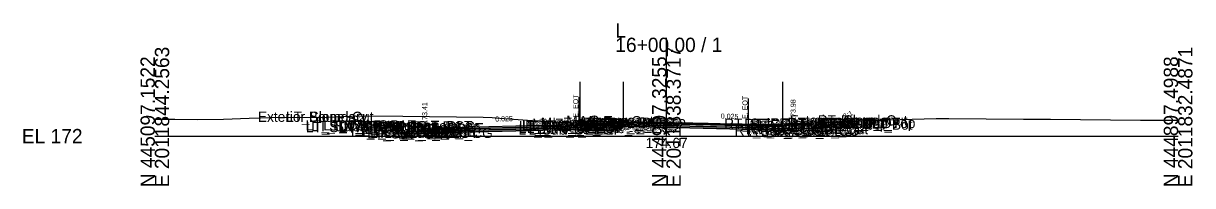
# Model space of a CAD drawing. Extents: x -26 to 4203, y -10 to 9526.
# Drawn here: x -25.7 to 202.8, y 5990.3 to 6022.1 of the extents above; entities that cross this region are included whole.
import ezdxf

# ---------------------------------------------------------------- set-up
doc = ezdxf.new("R2010")
doc.units = 0
for name, color, linetype in [('Default', 7, 'Continuous'), ('Exist Cross Section Cell', 7, 'Continuous'), ('Exist XS Center Line Elevation Label', 7, 'Continuous'), ('Exist XS Ground Line', 7, 'Continuous'), ('Prop CMT Conc Surface', 7, 'Continuous'), ('Prop CMT Concrete Structures', 7, 'Continuous'), ('Prop CMT Pvmt Course 1', 7, 'Continuous'), ('Prop CMT Pvmt Course 1 CG', 7, 'Continuous'), ('Prop CMT Pvmt Course 2', 7, 'Continuous'), ('Prop CMT Pvmt Course 3', 7, 'Continuous'), ('Prop CMT Pvmt Surface', 7, 'Continuous'), ('Prop CMT Slope Grass', 7, 'Continuous'), ('Prop CMT Subgrade Earthwork', 7, 'Continuous'), ('Prop XS Hydro Elevations', 7, 'Continuous'), ('Prop XS Label Text', 7, 'Continuous'), ('Prop XS SE Text', 7, 'Continuous'), ('Prop XS Side Slope Text', 7, 'Continuous'), ('Scratch_Level_0', 7, 'Continuous'), ('Scratch_Level_3', 7, 'Continuous')]:
    doc.layers.add(name, color=color, linetype=linetype)

msp = doc.modelspace()

# ---------------------------------------------------------------- linework, layer by layer
at = {"layer": 'Exist Cross Section Cell'}
for p, q in [((100, 6000), (100, 6019.26)), ((0, 6000), (100, 6000)), ((100, 6000), (200, 6000))]:
    msp.add_line(p, q, dxfattribs=at)
at = {"layer": 'Exist XS Ground Line'}
msp.add_lwpolyline([(0, 6003.3), (3.93, 6003.34), (8.4, 6003.25), (13.39, 6003.33), (18.42, 6003.52), (22.85, 6003.62), (28.44, 6003.68), (32.31, 6003.64), (38.46, 6003.89), (41.77, 6003.96), (48.48, 6003.9), (64.15, 6003.68), (65.91, 6003.65), (66.51, 6003.6), (76.4, 6002.89), (81.51, 6002.6), (82.34, 6002.6), (82.87, 6002.6), (84.32, 6002.6), (84.76, 6002.61), (86.85, 6002.6), (87.23, 6002.6), (89.24, 6002.63), (89.76, 6002.64), (91.62, 6002.63), (92.28, 6002.64), (92.77, 6002.65), (94.08, 6002.67), (94.78, 6002.67), (96.34, 6002.66), (97.26, 6002.66), (98.31, 6002.66), (100, 6002.67), (100.98, 6002.65), (102.28, 6002.62), (103.62, 6002.6), (105.17, 6002.58), (106.42, 6002.54), (107.24, 6002.52), (108.12, 6002.5), (109.75, 6002.48), (110.5, 6002.46), (112.27, 6002.4), (114.28, 6002.38), (114.77, 6002.37), (115.96, 6002.34), (117.15, 6002.3), (117.52, 6002.29), (124.56, 6002.47), (128.63, 6002.62), (130.55, 6002.71), (138.65, 6003.04), (152.71, 6003.45), (153.51, 6003.46), (155.19, 6003.44), (169.8, 6003.33), (171.37, 6003.34), (175.06, 6003.3), (192.64, 6003.15), (194.12, 6003.14), (197.4, 6003.13), (200, 6003.12)], dxfattribs=at)
at = {"layer": 'Prop CMT Conc Surface'}
for points in [[(48.25, 6002), (43.25, 6002.1)], [(52.75, 6001.41), (52.75, 6001.91), (52.25, 6001.91)], [(54.75, 6001.54), (52.75, 6001.41)], [(122.76, 6002.11), (124.76, 6001.98)], [(124.76, 6001.98), (124.76, 6002.48), (125.26, 6002.48)], [(129.26, 6002.57), (134.26, 6002.67)]]:
    msp.add_lwpolyline(points, dxfattribs=at)
at = {"layer": 'Prop CMT Concrete Structures'}
for p, q in [((83.85, 6002.77), (83.11, 6002.5)), ((83.11, 6002.5), (83.11, 6002.33)), ((88.1, 6003.24), (83.85, 6002.77)), ((90.84, 6003.28), (88.1, 6003.24)), ((91.6, 6003.05), (90.84, 6003.28)), ((91.61, 6002.88), (91.6, 6003.05))]:
    msp.add_line(p, q, dxfattribs=at)
for points in [[(43.25, 6001.77), (43.25, 6002.1)], [(43.25, 6002.1), (48.25, 6002)], [(48.25, 6001.67), (43.25, 6001.77)], [(48.25, 6002), (48.25, 6001.67)], [(54.75, 6001.54), (52.75, 6001.41), (52.75, 6001.91), (52.25, 6001.91)], [(52.25, 6001.91), (52.25, 6000.9), (54.75, 6000.96)], [(54.75, 6000.96), (54.75, 6001.54)], [(83.11, 6002.33), (91.61, 6002.88)], [(122.76, 6002.11), (124.76, 6001.98), (124.76, 6002.48), (125.26, 6002.48)], [(125.26, 6002.48), (125.26, 6001.46), (122.76, 6001.52)], [(122.76, 6001.52), (122.76, 6002.11)], [(134.26, 6002.67), (129.26, 6002.57)], [(129.26, 6002.57), (129.26, 6002.23)], [(129.26, 6002.23), (134.26, 6002.33)], [(134.26, 6002.33), (134.26, 6002.67)]]:
    msp.add_lwpolyline(points, dxfattribs=at)
at = {"layer": 'Prop CMT Pvmt Course 1'}
for points in [[(81.09, 6002.2), (54.75, 6001.54)], [(54.75, 6001.29), (81.09, 6001.95)], [(54.75, 6001.54), (54.75, 6001.29)], [(81.09, 6002.2), (91.61, 6002.88)], [(91.61, 6002.63), (81.09, 6001.95)], [(81.09, 6001.95), (81.09, 6002.2)], [(81.09, 6001.95), (81.09, 6002.2)], [(91.61, 6002.88), (122.76, 6002.11)], [(91.61, 6002.63), (91.61, 6002.88)], [(91.61, 6002.63), (91.61, 6002.88)], [(122.76, 6001.86), (91.61, 6002.63)], [(122.76, 6002.11), (122.76, 6001.86)]]:
    msp.add_lwpolyline(points, dxfattribs=at)
for points in [[(81.09, 6001.95), (81.09, 6002.08), (81.09, 6002.08), (81.09, 6001.95)], [(91.61, 6002.63), (91.61, 6002.76), (91.61, 6002.76), (91.61, 6002.63)]]:
    msp.add_lwpolyline(points, close=True, dxfattribs=at)
at = {"layer": 'Prop CMT Pvmt Course 1 CG'}
for points in [[(122.76, 6001.52), (125.76, 6001.45), (126.1, 6001.1)], [(122.76, 6001.19), (122.76, 6001.52)], [(54.75, 6000.96), (51.75, 6000.88), (51.41, 6000.54)], [(51.41, 6000.54), (54.75, 6000.63)], [(54.75, 6000.63), (54.75, 6000.96)], [(126.1, 6001.1), (122.76, 6001.19)]]:
    msp.add_lwpolyline(points, dxfattribs=at)
at = {"layer": 'Prop CMT Pvmt Course 2'}
for points in [[(81.09, 6001.95), (54.75, 6001.29)], [(54.75, 6000.96), (81.09, 6001.62)], [(54.75, 6001.29), (54.75, 6000.96)], [(81.09, 6001.95), (91.61, 6002.63)], [(91.61, 6002.3), (81.09, 6001.62)], [(81.09, 6001.62), (81.09, 6001.95)], [(81.09, 6001.62), (81.09, 6001.95)], [(91.61, 6002.63), (122.76, 6001.86)], [(91.61, 6002.3), (91.61, 6002.63)], [(91.61, 6002.3), (91.61, 6002.63)], [(122.76, 6001.52), (91.61, 6002.3)], [(122.76, 6001.86), (122.76, 6001.52)]]:
    msp.add_lwpolyline(points, dxfattribs=at)
at = {"layer": 'Prop CMT Pvmt Course 3'}
for points in [[(81.09, 6001.62), (54.75, 6000.96)], [(54.75, 6000.63), (81.09, 6001.28)], [(81.09, 6001.62), (91.61, 6002.3)], [(91.61, 6001.97), (81.09, 6001.28)], [(81.09, 6001.28), (81.09, 6001.62)], [(81.09, 6001.28), (81.09, 6001.62)], [(91.61, 6002.3), (122.76, 6001.52)], [(91.61, 6001.97), (91.61, 6002.3)], [(91.61, 6001.97), (91.61, 6002.3)], [(122.76, 6001.19), (91.61, 6001.97)], [(122.76, 6001.52), (122.76, 6001.19)], [(54.75, 6000.96), (54.75, 6000.63)]]:
    msp.add_lwpolyline(points, dxfattribs=at)
at = {"layer": 'Prop CMT Pvmt Surface'}
for points in [[(81.09, 6002.2), (54.75, 6001.54)], [(81.09, 6002.2), (91.61, 6002.88)], [(91.61, 6002.88), (122.76, 6002.11)]]:
    msp.add_lwpolyline(points, dxfattribs=at)
at = {"layer": 'Prop CMT Slope Grass'}
for p, q in [((37.5, 6003.85), (42.75, 6002.1)), ((134.76, 6002.67), (135.5, 6002.91))]:
    msp.add_line(p, q, dxfattribs=at)
for points in [[(52.25, 6001.91), (42.75, 6002.1)], [(125.26, 6002.48), (134.26, 6002.66)], [(134.26, 6002.66), (134.76, 6002.67)]]:
    msp.add_lwpolyline(points, dxfattribs=at)
at = {"layer": 'Prop CMT Subgrade Earthwork'}
for points in [[(54.75, 6000.63), (51.41, 6000.54), (49.99, 6001.96)], [(81.09, 6001.28), (54.75, 6000.63)], [(81.09, 6001.28), (91.61, 6001.97)], [(91.61, 6001.97), (122.76, 6001.19)], [(122.76, 6001.19), (126.1, 6001.1), (127.51, 6002.52)]]:
    msp.add_lwpolyline(points, dxfattribs=at)
at = {"layer": 'Prop XS Label Text'}
for p, q in [((82.87, 6007.6), (82.87, 6002.6)), ((115.96, 6007.34), (115.96, 6002.34))]:
    msp.add_line(p, q, dxfattribs=at)
at = {"layer": 'Scratch_Level_3'}
for p, q in [((83.11, 6002.33), (83.11, 6010.61)), ((91.61, 6002.88), (91.61, 6010.61)), ((122.76, 6002.11), (122.76, 6010.61))]:
    msp.add_line(p, q, dxfattribs=at)

# ---------------------------------------------------------------- texts
at = {"layer": 'Default'}
msp.add_text('-', height=0.0001, dxfattribs=at).set_placement((0, 6000))
at = {"layer": 'Exist Cross Section Cell'}
for s, p in [('L', (90, 6019.26)), ('16+00.00 / 1', (90, 6016.46)), ('EL 172', (-26, 5998.6))]:
    msp.add_text(s, height=2.8, dxfattribs=at).set_placement(p)
for s, p in [('E 2011844.2563', (2.8, 5990)), ('E 2011838.3717', (102.8, 5990)), ('E 2011832.4871', (202.8, 5990)), ('N 445097.1522', (0, 5990)), ('N 444997.3255', (100, 5990)), ('N 444897.4988', (200, 5990))]:
    msp.add_text(s, height=2.8, rotation=90, dxfattribs=at).set_placement(p)
at = {"layer": 'Exist XS Center Line Elevation Label'}
msp.add_text('174.67', height=2, dxfattribs=at).set_placement((95.94, 5997.67))
at = {"layer": 'Prop XS Hydro Elevations'}
for s, p in [('173.41', (53.25, 6002.41)), ('173.98', (125.26, 6002.98))]:
    msp.add_text(s, height=1, rotation=90, dxfattribs=at).set_placement(p)
at = {"layer": 'Prop XS Label Text'}
for p in [(82.77, 6003.62), (115.86, 6003.36)]:
    msp.add_text('E. EOT', height=1, rotation=90, dxfattribs=at).set_placement(p)
at = {"layer": 'Prop XS SE Text'}
for rotation, p in [(1.4333, (66.54, 6002.84)), (358.568, (110.6, 6003.42))]:
    msp.add_text('0.025', height=1, rotation=rotation, dxfattribs=at).set_placement(p)
at = {"layer": 'Prop XS Side Slope Text'}
for rotation, p in [(341.5651, (39.09, 6003.84)), (26.4229, (134.82, 6003.33))]:
    msp.add_text('3:1', height=1, rotation=rotation, dxfattribs=at).set_placement(p)
at = {"layer": 'Scratch_Level_0'}
for s, p in [('Exterior Boundary', (20.15, 6002.79)), ('LT_Slope_Cut', (25.64, 6002.79)), ('MI_Top In', (75.45, 6001.64)), ('MI_Crown', (80.43, 6002.01)), ('MI_Face Out', (83.13, 6001.66)), ('MI_Top Out', (83.34, 6001.91)), ('RT_PV2_PGL1', (83.7, 6001.6)), ('RT_SDWK_Out_Top', (123.69, 6001.58)), ('Exterior Boundary', (124.12, 6002.08)), ('RT_Slope_Cut', (129.57, 6002.08)), ('RT_Shld_O', (130.04, 6001.57)), ('CSLP_Pnt', (130.87, 6001.58)), ('LT_SDWK_Out_Top', (29.48, 6001.1)), ('LT_SDWK_Out_Bot', (29.51, 6000.77)), ('LT_Sub_Trench_Out_DLT', (30.56, 6000.96)), ('LT_CSLP_Pnt', (32.92, 6001.1)), ('LT_SDWK_In_Top', (36.1, 6001)), ('LT_SDWK_In_Bot', (36.14, 6000.67)), ('LT_CG1_Shelf_Out', (38.3, 5999.88)), ('LT_CG_Top_Face', (40.01, 6000.91)), ('LT_CG_Top_BOC', (40.53, 6000.91)), ('LT_CG_Bot_BOC', (40.56, 5999.9)), ('LT_CG_Top_Gut', (40.98, 6000.41)), ('LT_Sub_OEOP', (41.52, 5999.54)), ('LT_Sub_OEOT_CG', (42.12, 5999.63)), ('LT_CG_Bot_IE', (44.66, 5999.96)), ('LT_Sub_OEOT', (44.83, 5999.63)), ('LT_PV2_OEOT', (44.92, 6000.29)), ('LT_PV3_OEOT', (44.92, 5999.96)), ('LT_PV1_OEOT', (45.49, 6000.54)), ('LT_Sub_OEEOP', (71.06, 6000.3)), ('LT_PV2_OEEOP', (71.15, 6000.97)), ('LT_PV3_OEEOP', (71.15, 6000.64)), ('LT_PV1_OEEOP', (71.72, 6001.09)), ('LT_PV2_IEEOP', (71.8, 6000.97)), ('LT_PV1_IEEOP', (72.36, 6001.09)), ('LT_PV2_PGL1', (72.73, 6000.97)), ('LT_PV3_PGL1', (72.73, 6000.64)), ('LT_PV2_PGL', (73.06, 6000.97)), ('LT_PV4_PGL', (73.06, 6000.3)), ('LT_PV1_PGL', (73.62, 6001.22)), ('MI_Face In', (73.74, 6001.39)), ('RT_Sub_OEEOP', (82.03, 6000.58)), ('RT_PV2_OEEOP', (82.13, 6001.24)), ('RT_PV3_OEEOP', (82.13, 6000.91)), ('RT_PV1_OEEOP', (82.7, 6001.37)), ('RT_PV2_IEEOP', (82.77, 6001.24)), ('RT_PV1_IEEOP', (83.34, 6001.37)), ('RT_PV3_PGL1', (83.7, 6001.27)), ('RT_PV2_PGL', (84.03, 6001.24)), ('RT_PV4_PGL', (84.03, 6000.93)), ('MI_Bot Out', (84.13, 6001.5)), ('RT_PV1_PGL', (84.6, 6001.5)), ('RT_Sub_Trench_Out_DLT', (111.28, 6001.44)), ('RT_Sub_OEOT_CG', (113.32, 6000.11)), ('RT_CG_Top_Face', (115.21, 6001.39)), ('RT_CG1_Shelf_Out', (115.5, 6000.36)), ('RT_CG_Bot_IE', (115.87, 6000.44)), ('RT_Sub_OEOT', (116.03, 6000.11)), ('RT_PV2_OEOT', (116.13, 6000.77)), ('RT_PV3_OEOT', (116.13, 6000.44)), ('RT_CG_Top_Gut', (116.19, 6000.89)), ('RT_PV1_OEOT', (116.69, 6001.02)), ('RT_CG_Top_BOC', (116.74, 6001.39)), ('RT_CG_Bot_BOC', (116.77, 6000.38)), ('RT_Sub_OEOP', (119.41, 6000.02)), ('RT_SDWK_In_Top', (120.31, 6001.48)), ('RT_SDWK_In_Bot', (120.34, 6001.15)), ('RT_SDWK_Out_Bot', (123.72, 6001.25))]:
    msp.add_text(s, height=2, dxfattribs=at).set_placement(p)

doc.saveas('drawing.dxf')
